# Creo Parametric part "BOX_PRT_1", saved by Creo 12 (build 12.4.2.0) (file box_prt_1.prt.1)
Units: Custom; MM, KILOGRAM, SECS

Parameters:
  PTC_WM_ITERATION = "0"
  PTC_WM_VERSION = "-.0"
  PTC_WM_LIFECYCLE_STATE = "In Work"
  PTC_WM_LIFECYCLE = "MO_CADDocument"
  PTC_WM_CREATED_BY = "Maximilian Roepper (Z0017RMS: MO)"
  PTC_WM_CREATED_ON = "18-Sep-26 11:36:42 AM"
  PTC_WM_MODIFIED_BY = "Maximilian Roepper (Z0017RMS: MO)"
  PTC_WM_MODIFIED_ON = "18-Sep-26 11:36:46 AM"
  PDMLINKNUMBER = "PDM000071454949"
  PTC_WM_NAME = "box_prt_1.prt"
  PTC_WM_NUMBER = "PDM000071454949"

Other parameters: WEIGHT, WEIGHT_FACTOR, WEIGHT_ADD, _MASS_TEMP, _DIFF_TEMP, MC_ERRORS, SUPPLIER

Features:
  1. coordinate system
  2. datum plane "PRT_YZ"
  3. datum plane "PRT_XY"
  4. datum plane "PRT_XZ"
  5. coordinate system
  6. datum axis
  7. datum axis
  8. datum axis
  9. coordinate system
  10. imported feature
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
Other named items: PRT, SIEMENS_MO, DRW_VIEW_ORG, PRT_X, PRT_Y, PRT_Z, CS0, ROUGH_GROB

Layers: 00_STD_CSYS-KSYS, 01_STD_PLANES-EBENEN, 02_STD_AXES-ACHSEN, 03_STD_CSYS-KSYS, 24_IMPORT_FEAT-IMPORT_KE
